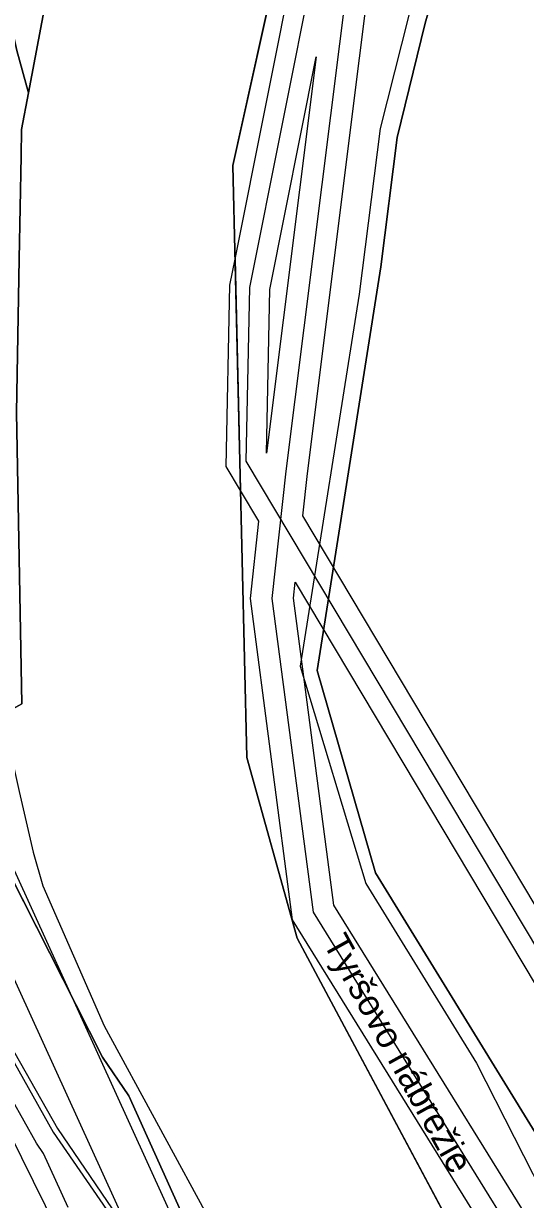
# Model space of a CAD drawing. Extents: x -264070 to -262271, y -1238894 to -1238141.
# Drawn here: x -262952.2 to -262913.5, y -1238467.1 to -1238376.5 of the extents above; entities that cross this region are included whole.
import ezdxf

# ---------------------------------------------------------------- set-up
doc = ezdxf.new("R2010")
doc.units = 0
for name, color, linetype in [('body_kn', 7, 'Continuous'), ('kladpar_hranice', 7, 'Continuous'), ('kladpar_plochy', 7, 'Continuous'), ('popisy', 7, 'Continuous'), ('tarchy_linie', 7, 'Continuous'), ('zappar_hrandruhpozemk', 7, 'Continuous')]:
    doc.layers.add(name, color=color, linetype=linetype)

msp = doc.modelspace()

# ---------------------------------------------------------------- linework, layer by layer
at = {"layer": 'body_kn'}
for p, q in [((-262929.65, -1238379.06), (-262929.65, -1238379.06)), ((-262951.84, -1238381.85), (-262951.84, -1238381.85)), ((-262951.84, -1238381.85), (-262951.84, -1238381.85)), ((-262924.73, -1238384.59), (-262924.73, -1238384.59)), ((-262923.4, -1238385.27), (-262923.4, -1238385.27)), ((-262936.08, -1238387.45), (-262936.08, -1238387.45)), ((-262935.91, -1238394.66), (-262935.91, -1238394.66)), ((-262924.66, -1238395.24), (-262924.66, -1238395.24)), ((-262936.32, -1238396.67), (-262936.32, -1238396.67)), ((-262934.77, -1238396.84), (-262934.77, -1238396.84)), ((-262933.23, -1238397.01), (-262933.23, -1238397.01)), ((-262926.35, -1238397.35), (-262926.35, -1238397.35)), ((-262933.49, -1238409.6), (-262933.49, -1238409.6)), ((-262933.49, -1238409.6), (-262933.49, -1238409.6)), ((-262936.6, -1238410.63), (-262936.6, -1238410.63)), ((-262935.04, -1238410.22), (-262935.04, -1238410.22)), ((-262932, -1238411), (-262932, -1238411)), ((-262930.36, -1238411.19), (-262930.36, -1238411.19)), ((-262935.48, -1238412.48), (-262935.48, -1238412.48)), ((-262935.48, -1238412.48), (-262935.48, -1238412.48)), ((-262930.72, -1238414.44), (-262930.72, -1238414.44)), ((-262934.08, -1238414.85), (-262934.08, -1238414.85)), ((-262931.27, -1238419.55), (-262931.27, -1238419.55)), ((-262934.73, -1238420.82), (-262934.73, -1238420.82)), ((-262933.07, -1238420.81), (-262933.07, -1238420.81)), ((-262931.41, -1238420.8), (-262931.41, -1238420.8)), ((-262930.89, -1238426.04), (-262930.89, -1238426.04)), ((-262929.57, -1238426.37), (-262929.57, -1238426.37)), ((-262934.99, -1238433.06), (-262934.99, -1238433.06)), ((-262951.48, -1238440.36), (-262951.48, -1238440.36)), ((-262925.07, -1238441.97), (-262925.07, -1238441.97)), ((-262950.74, -1238442.96), (-262950.74, -1238442.96)), ((-262925.82, -1238442.79), (-262925.82, -1238442.79)), ((-262928.29, -1238444.44), (-262928.29, -1238444.44)), ((-262929.88, -1238445), (-262929.88, -1238445)), ((-262931.47, -1238445.57), (-262931.47, -1238445.57)), ((-262931.12, -1238447), (-262931.12, -1238447)), ((-262946, -1238453.75), (-262946, -1238453.75)), ((-262946.12, -1238456.17), (-262946.12, -1238456.17)), ((-262917.3, -1238456.62), (-262917.3, -1238456.62)), ((-262944.09, -1238459.15), (-262944.09, -1238459.15)), ((-262949.59, -1238461.67), (-262949.59, -1238461.67)), ((-262949.94, -1238461.94), (-262949.94, -1238461.94)), ((-262951.23, -1238462.8), (-262951.23, -1238462.8)), ((-262950.68, -1238463.6), (-262950.68, -1238463.6))]:
    msp.add_line(p, q, dxfattribs=at)
at = {"layer": 'kladpar_hranice'}
for points in [[(-262938.08, -1238472.48), (-262944.09, -1238459.15), (-262946.12, -1238456.17), (-262958.52, -1238431.77), (-262957.85, -1238431.45), (-262953.86, -1238429.77), (-262952.34, -1238428.93), (-262952.76, -1238406.47), (-262952.55, -1238394.64), (-262952.41, -1238386.72), (-262952.37, -1238384.66), (-262951.84, -1238381.85), (-262948.94, -1238366.42), (-262944.5, -1238346.95), (-262942.49, -1238340.81), (-262938.85, -1238330.13), (-262935.17, -1238320.85), (-262926.88, -1238292.79), (-262923.23, -1238282.93), (-262919.35, -1238266.96), (-262916.31, -1238256.88), (-262915.44, -1238253.09), (-262898.67, -1238252.06)], [(-262912.96, -1238299.77), (-262921.54, -1238329.59), (-262928.62, -1238353.76), (-262936.08, -1238387.45), (-262934.99, -1238433.06), (-262931.12, -1238447), (-262910.65, -1238485.29)], [(-262910.65, -1238485.29), (-262931.12, -1238447), (-262934.99, -1238433.06), (-262936.08, -1238387.45), (-262928.62, -1238353.76), (-262921.54, -1238329.59)], [(-262912.27, -1238338.49), (-262915.11, -1238349.24), (-262915.62, -1238349.14), (-262915.41, -1238351.37), (-262915, -1238352.83), (-262914.59, -1238353.93), (-262917.73, -1238364.43), (-262918.33, -1238366.45), (-262918.98, -1238368.62), (-262921.26, -1238376.48), (-262923.4, -1238385.27), (-262924.66, -1238395.24), (-262929.57, -1238426.37), (-262925.07, -1238441.97), (-262912.76, -1238461.97)], [(-262942.49, -1238340.81), (-262944.5, -1238346.95), (-262948.94, -1238366.42), (-262951.84, -1238381.85), (-262952.73, -1238378.57), (-262953.25, -1238376.26), (-262953.93, -1238372.72), (-262954.34, -1238369.75), (-262954.66, -1238366.74), (-262954.44, -1238363.72), (-262953.43, -1238360.01), (-262951.31, -1238352.22), (-262948.94, -1238344.39), (-262948.47, -1238344.14), (-262942.49, -1238340.81)], [(-262951.84, -1238381.85), (-262952.37, -1238384.66), (-262952.41, -1238386.72), (-262952.55, -1238394.64), (-262952.76, -1238406.47), (-262952.34, -1238428.93), (-262953.86, -1238429.77), (-262957.85, -1238431.45), (-262968.09, -1238412.47), (-262980.46, -1238391.76), (-263001.91, -1238356.1), (-262986.84, -1238347.85), (-262986.56, -1238347.69), (-262985.79, -1238349.18), (-262985.19, -1238350.59), (-262968, -1238384.43), (-262966.63, -1238383.67), (-262962.62, -1238381.45), (-262956.19, -1238377.89), (-262953.25, -1238376.26), (-262952.73, -1238378.57), (-262951.84, -1238381.85)], [(-263001.91, -1238356.1), (-262980.46, -1238391.76), (-262968.09, -1238412.47), (-262957.85, -1238431.45), (-262958.52, -1238431.77), (-262946.12, -1238456.17), (-262944.09, -1238459.15), (-262938.08, -1238472.48), (-262924.76, -1238500.02), (-262919.42, -1238511.83), (-262907.79, -1238536.85)], [(-262813.03, -1238423.69), (-262816.48, -1238412.84), (-262832.44, -1238417.74), (-262850.86, -1238423.39), (-262870.49, -1238429.42), (-262871.1, -1238427.48), (-262888.61, -1238433.21), (-262885.22, -1238444.06), (-262877.38, -1238441.43), (-262874.97, -1238450.05), (-262873.29, -1238475.29), (-262869.12, -1238488.27), (-262868.55, -1238519.74), (-262897.95, -1238490.56), (-262896.25, -1238489.53), (-262912.76, -1238461.97), (-262925.07, -1238441.97), (-262929.57, -1238426.37), (-262924.66, -1238395.24), (-262923.4, -1238385.27), (-262921.26, -1238376.48), (-262918.98, -1238368.62), (-262909.71, -1238368.87)]]:
    msp.add_lwpolyline(points, dxfattribs=at)
at = {"layer": 'kladpar_plochy'}
for p, q in [((-262928.62, -1238353.76), (-262936.08, -1238387.45)), ((-262951.84, -1238381.85), (-262948.94, -1238366.42)), ((-262923.4, -1238385.27), (-262921.26, -1238376.48)), ((-262952.37, -1238384.66), (-262951.84, -1238381.85)), ((-262924.66, -1238395.24), (-262923.4, -1238385.27)), ((-262936.08, -1238387.45), (-262934.99, -1238433.06)), ((-262929.57, -1238426.37), (-262924.66, -1238395.24)), ((-262925.07, -1238441.97), (-262929.57, -1238426.37)), ((-262946.12, -1238456.17), (-262958.52, -1238431.77)), ((-262934.99, -1238433.06), (-262931.12, -1238447)), ((-262912.76, -1238461.97), (-262925.07, -1238441.97)), ((-262931.12, -1238447), (-262910.65, -1238485.29)), ((-262944.09, -1238459.15), (-262946.12, -1238456.17)), ((-262938.08, -1238472.48), (-262944.09, -1238459.15))]:
    msp.add_line(p, q, dxfattribs=at)
for points in [[(-262910.65, -1238485.29), (-262931.12, -1238447), (-262934.99, -1238433.06), (-262936.08, -1238387.45), (-262928.62, -1238353.76), (-262921.54, -1238329.59), (-262912.96, -1238299.77)], [(-263028.23, -1238312.73), (-263011.78, -1238341.08), (-263001.91, -1238356.1), (-262980.46, -1238391.76), (-262968.09, -1238412.47), (-262957.85, -1238431.45), (-262958.52, -1238431.77), (-262946.12, -1238456.17), (-262944.09, -1238459.15), (-262938.08, -1238472.48)], [(-262912.27, -1238338.49), (-262915.11, -1238349.24), (-262915.62, -1238349.14), (-262915.41, -1238351.37), (-262915, -1238352.83), (-262914.59, -1238353.93), (-262917.73, -1238364.43), (-262918.33, -1238366.45), (-262918.98, -1238368.62), (-262921.26, -1238376.48), (-262923.4, -1238385.27), (-262924.66, -1238395.24), (-262929.57, -1238426.37), (-262925.07, -1238441.97), (-262912.76, -1238461.97)]]:
    msp.add_lwpolyline(points, dxfattribs=at)
for points in [[(-262942.49, -1238340.81), (-262944.5, -1238346.95), (-262948.94, -1238366.42), (-262951.84, -1238381.85), (-262952.73, -1238378.57), (-262953.25, -1238376.26), (-262953.93, -1238372.72), (-262954.34, -1238369.75), (-262954.66, -1238366.74), (-262954.44, -1238363.72), (-262953.43, -1238360.01), (-262951.31, -1238352.22), (-262948.94, -1238344.39), (-262948.47, -1238344.14)], [(-262951.84, -1238381.85), (-262952.37, -1238384.66), (-262952.41, -1238386.72), (-262952.55, -1238394.64), (-262952.76, -1238406.47), (-262952.34, -1238428.93), (-262953.86, -1238429.77), (-262957.85, -1238431.45), (-262968.09, -1238412.47), (-262980.46, -1238391.76), (-263001.91, -1238356.1), (-262986.84, -1238347.85), (-262986.56, -1238347.69), (-262985.79, -1238349.18), (-262985.19, -1238350.59), (-262968, -1238384.43), (-262966.63, -1238383.67), (-262962.62, -1238381.45), (-262956.19, -1238377.89), (-262953.25, -1238376.26), (-262952.73, -1238378.57)]]:
    msp.add_lwpolyline(points, close=True, dxfattribs=at)
at = {"layer": 'tarchy_linie'}
for points in [[(-262782.79, -1238737.49), (-262819.96, -1238648.88), (-262858.02, -1238549.05), (-262898.92, -1238470.7), (-262935.04, -1238410.22), (-262934.77, -1238396.84), (-262927.28, -1238359.37), (-262901.86, -1238273.51), (-262894.05, -1238251.13)], [(-262892.23, -1238250.77), (-262903.56, -1238282.44), (-262914.22, -1238322.11), (-262925.77, -1238361.47), (-262932, -1238411), (-262933.07, -1238420.81), (-262929.88, -1238445), (-262902, -1238490), (-262879.2, -1238520.11), (-262865.84, -1238538.82), (-262846.84, -1238581.58), (-262829.05, -1238624.25), (-262812.41, -1238667.65), (-262795.14, -1238711.11), (-262786, -1238738.54)], [(-262903.36, -1238490.94), (-262931.47, -1238445.57), (-262934.73, -1238420.82), (-262934.08, -1238414.85), (-262935.48, -1238412.48), (-262935.91, -1238394.66), (-262928.75, -1238358.85), (-262903.34, -1238273.03)], [(-263038.59, -1238278.01), (-263038.81, -1238283.6), (-263023.76, -1238334.4), (-263004.35, -1238368.98), (-262988.5, -1238396.63), (-262970, -1238425.7), (-262949.59, -1238461.67), (-262929.74, -1238490.84), (-262915.64, -1238510.07), (-262911.62, -1238516.37), (-262904.25, -1238532.08), (-262899.49, -1238561.55), (-262883.46, -1238603.14), (-262855.12, -1238679.37), (-262825.32, -1238749.06), (-262831.6, -1238762.46)], [(-263049.81, -1238282.44), (-263016.2, -1238342.64), (-262978.3, -1238405.77), (-262957.24, -1238440.79), (-262909.76, -1238544.87), (-262886.28, -1238607.09), (-262862.09, -1238671.7), (-262834.14, -1238746.5), (-262835.49, -1238761.73)], [(-262948.78, -1238467.76), (-262950.68, -1238463.6), (-262951.23, -1238462.8), (-262954.1, -1238457.7), (-262956.07, -1238453.77), (-262962.09, -1238442.6), (-262965.81, -1238436.82), (-262971.53, -1238426.62), (-262982.46, -1238409.51), (-262990.04, -1238397.47), (-263025.67, -1238337.91), (-263039.23, -1238317.05), (-263052.69, -1238293.02), (-263056.53, -1238285.71), (-263056.4, -1238285.69)], [(-263055.03, -1238285.01), (-263051.32, -1238292.29), (-263037.9, -1238316.25), (-263024.35, -1238337.09), (-262999.02, -1238379.63), (-262988.72, -1238396.66), (-262981.15, -1238408.68), (-262970.2, -1238425.82), (-262949.94, -1238461.94), (-262926.84, -1238495.4), (-262921.43, -1238502.6), (-262915.89, -1238510.25), (-262914.81, -1238513.45), (-262908.31, -1238550.69), (-262885.94, -1238597.77), (-262863.52, -1238671.22), (-262830.98, -1238762.57)], [(-263025.48, -1238320.08), (-263017.88, -1238332.99), (-263013, -1238341.78), (-263004.33, -1238357.42), (-263001.36, -1238362.79), (-262996.8, -1238370.43), (-262995.91, -1238371.93), (-262995.38, -1238371.65), (-262994.3, -1238373.34), (-262994.91, -1238373.67), (-262989.53, -1238382.87), (-262982.03, -1238395.82), (-262973.48, -1238410.07), (-262972.59, -1238411.61), (-262962.69, -1238424.93), (-262954.14, -1238439.16), (-262936.28, -1238478.3)], [(-262912.63, -1238322.56), (-262922.95, -1238357.72), (-262915.67, -1238357.53), (-262916.13, -1238359.08), (-262916.76, -1238361.2), (-262917.28, -1238362.92), (-262924.32, -1238363.13), (-262930.36, -1238411.19), (-262930.72, -1238414.44), (-262897.57, -1238469.94)], [(-262933.49, -1238409.6), (-262933.23, -1238397.01), (-262929.65, -1238379.06), (-262933.49, -1238409.6)], [(-262935.48, -1238412.48), (-262936.6, -1238410.63), (-262936.32, -1238396.67), (-262935.91, -1238394.66), (-262935.48, -1238412.48)], [(-262900.27, -1238471.46), (-262868.65, -1238532.05), (-262877.87, -1238519.13), (-262900.64, -1238489.06), (-262928.29, -1238444.44), (-262931.41, -1238420.8), (-262931.27, -1238419.55), (-262900.27, -1238471.46)]]:
    msp.add_lwpolyline(points, dxfattribs=at)
at = {"layer": 'zappar_hrandruhpozemk'}
for p, q in [((-262924.73, -1238384.59), (-262926.35, -1238397.35)), ((-262946, -1238453.75), (-262929.65, -1238483.83)), ((-262917.3, -1238456.62), (-262910.25, -1238470.48))]:
    msp.add_line(p, q, dxfattribs=at)
for points in [[(-262917.73, -1238364.43), (-262918.87, -1238365.37), (-262920.87, -1238369.33), (-262924.73, -1238384.59)], [(-262926.35, -1238397.35), (-262930.89, -1238426.04), (-262925.82, -1238442.79), (-262917.3, -1238456.62)], [(-262953.86, -1238429.77), (-262952.57, -1238435.69), (-262951.48, -1238440.36), (-262950.74, -1238442.96), (-262946, -1238453.75)], [(-262954.23, -1238460.19), (-262942.37, -1238484.18), (-262934.63, -1238499.88), (-262917.89, -1238534.54)]]:
    msp.add_lwpolyline(points, dxfattribs=at)

# ---------------------------------------------------------------- texts
at = {"layer": 'popisy'}
msp.add_text('Tyršovo nábrežie', height=2, rotation=299, dxfattribs=at).set_placement((-262929.155, -1238447.381))

doc.saveas('drawing.dxf')
